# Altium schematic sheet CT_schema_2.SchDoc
size 313 x 185 mm
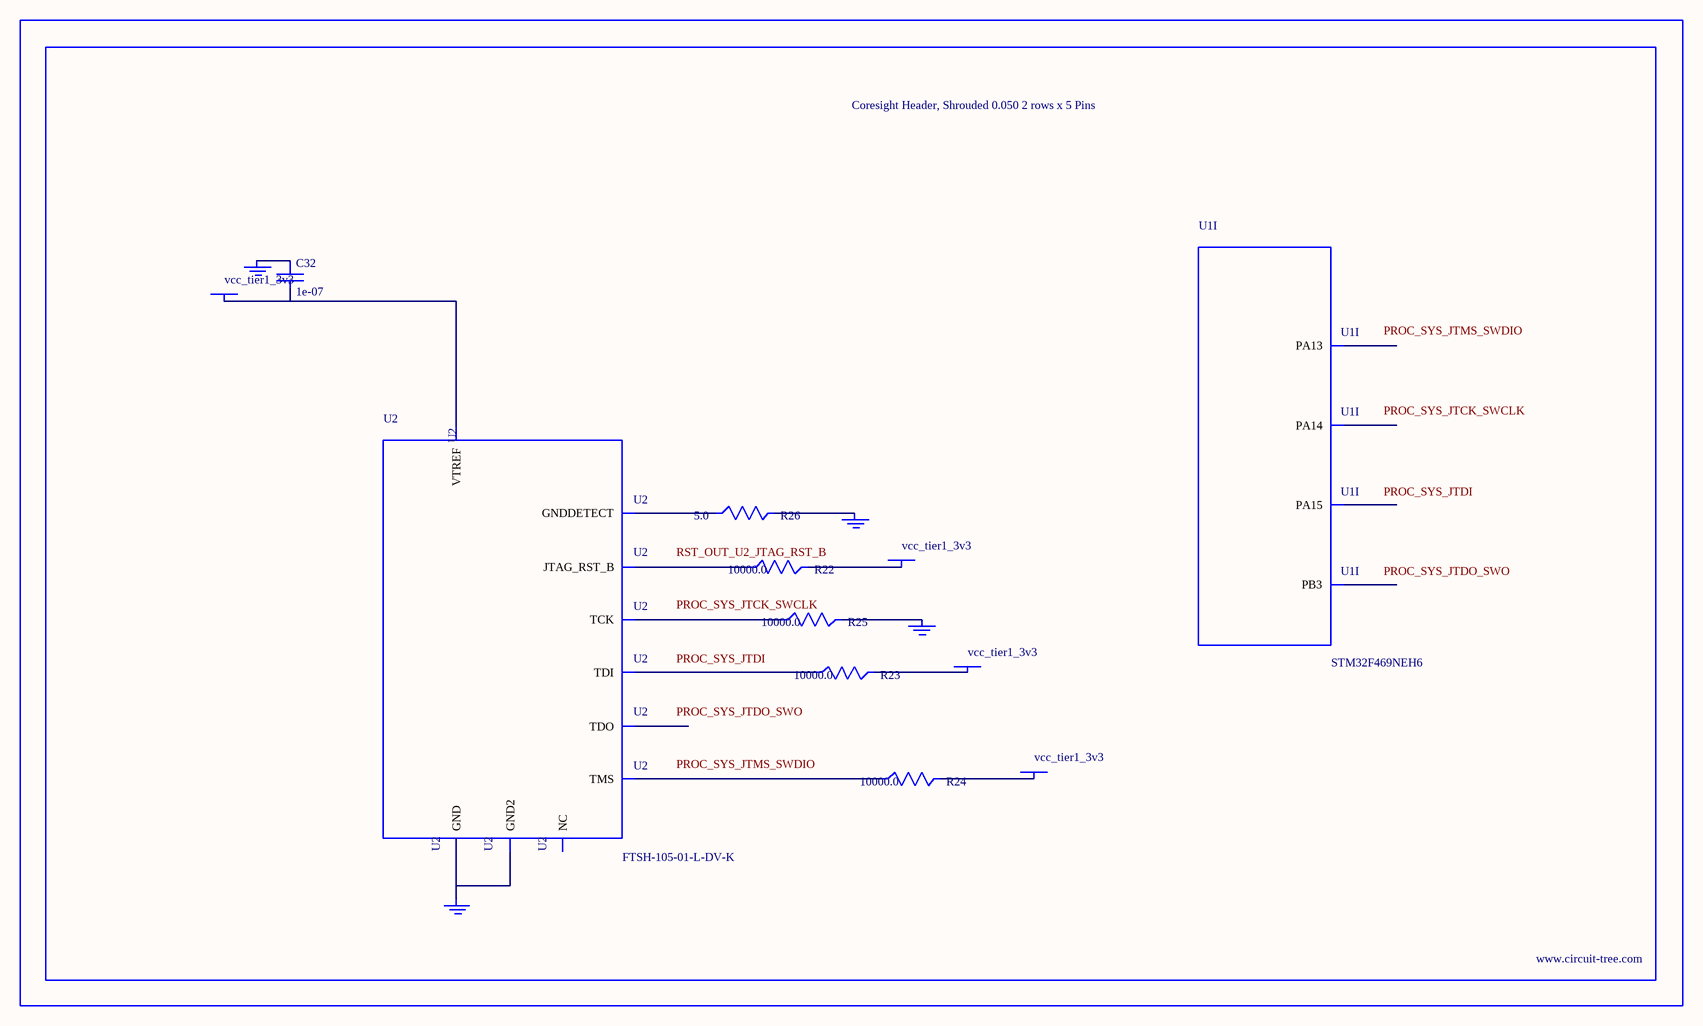
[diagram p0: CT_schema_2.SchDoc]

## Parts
BORDER1  (no value)
C32  1e-07  [C0402]
GND_INSTANCE_1_0  (no value)
GND_INSTANCE_1_1  (no value)
GND_INSTANCE_1_2  (no value)
GND_INSTANCE_1_3  (no value)
POWER_INSTANCE_1_0  vcc_tier1_3v3
POWER_INSTANCE_1_1  vcc_tier1_3v3
POWER_INSTANCE_1_2  vcc_tier1_3v3
POWER_INSTANCE_1_3  vcc_tier1_3v3
R22  10000.0  [R0603]
R23  10000.0  [R0603]
R24  10000.0  [R0603]
R25  10000.0  [R0603]
R26  5.0  [R0603]
U1  STM32F469NEH6  [TFBGA216]  (part I of 17)
U2  FTSH-105-01-L-DV-K  [SAMTEC_FTSH-105-01-L-DV-K]

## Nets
NetC32_1: C32.1 GND_INSTANCE_1_0.0(GND)
NetC32_2: C32.2 POWER_INSTANCE_1_0.0(PWR) U2.1(VTREF)
NetGND_INSTANCE_1_1_0: GND_INSTANCE_1_1.0(GND) R25.2
NetGND_INSTANCE_1_2_0: GND_INSTANCE_1_2.0(GND) R26.2
NetGND_INSTANCE_1_3_0: GND_INSTANCE_1_3.0(GND) U2.3(GND) U2.5(GND2)
NetPOWER_INSTANCE_1_1_0: POWER_INSTANCE_1_1.0(PWR) R24.2
NetPOWER_INSTANCE_1_2_0: POWER_INSTANCE_1_2.0(PWR) R23.2
NetPOWER_INSTANCE_1_3_0: POWER_INSTANCE_1_3.0(PWR) R22.2
NetR22_1: R22.1 U2.10(JTAG_RST_B)
NetR23_1: R23.1 U2.8(TDI)
NetR24_1: R24.1 U2.2(TMS)
NetR25_1: R25.1 U2.4(TCK)
NetR26_1: R26.1 U2.9(GNDDETECT)

Not connected (* = marked no-connect by the designer): U1 A10(PB3) A13(PA15) A14(PA14) A15(PA13); U2 6(TDO) 7(NC)

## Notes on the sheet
- Labels drawn without touching a wire or pin: PROC_SYS_JTCK_SWCLK, PROC_SYS_JTDI, PROC_SYS_JTDO_SWO, PROC_SYS_JTMS_SWDIO, RST_OUT_U2_JTAG_RST_B

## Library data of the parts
BORDER1 = BORDER_PAGE1
C32 = C0402C104K3RACTU
GND_INSTANCE_1_0-GND_INSTANCE_1_3 = GND
POWER_INSTANCE_1_0-POWER_INSTANCE_1_3 = PWR
R22-R25 = RC0603JR-0710KL
R26 = ERJ-3GEYJ5R1V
